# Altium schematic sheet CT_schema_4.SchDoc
size 252 x 159 mm
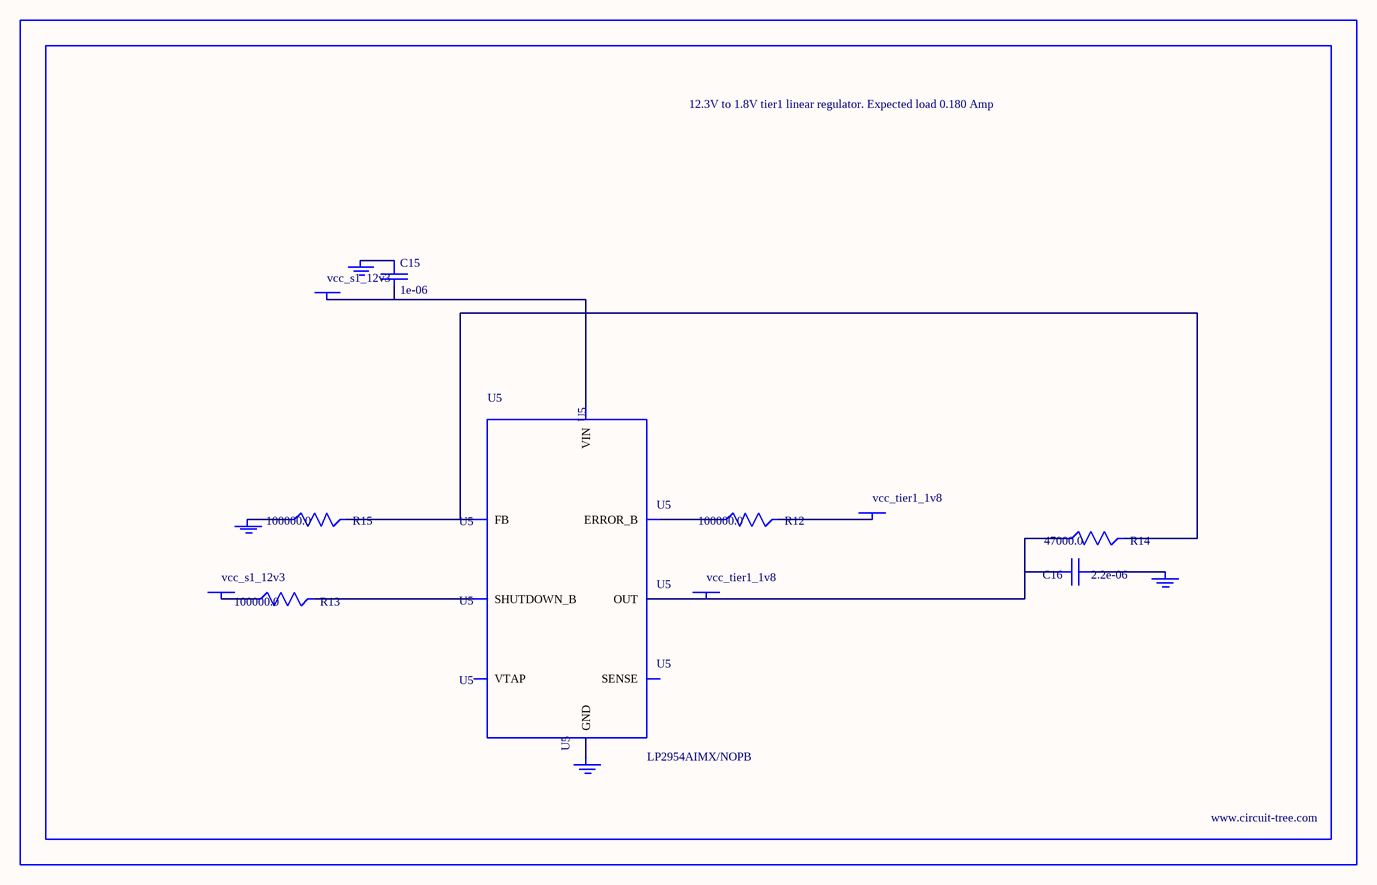
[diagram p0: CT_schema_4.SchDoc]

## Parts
BORDER3  (no value)
C15  1e-06  [EXV-9B]
C16  2.2e-06  [EXV-9B]
GND_INSTANCE_3_0  (no value)
GND_INSTANCE_3_1  (no value)
GND_INSTANCE_3_2  (no value)
GND_INSTANCE_3_3  (no value)
POWER_INSTANCE_3_0  vcc_s1_12v3
POWER_INSTANCE_3_1  vcc_tier1_1v8
POWER_INSTANCE_3_2  vcc_s1_12v3
POWER_INSTANCE_3_3  vcc_tier1_1v8
R12  100000.0  [R0603]
R13  100000.0  [R0603]
R14  47000.0  [R0603]
R15  100000.0  [R0603]
U5  LP2954AIMX/NOPB  [LP2954]

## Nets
NetC15_1: C15.1 GND_INSTANCE_3_2.0(GND)
NetC15_2: C15.2 POWER_INSTANCE_3_2.0(PWR) U5.8(VIN)
NetC16_1: C16.1 GND_INSTANCE_3_0.0(GND)
NetC16_2: C16.2 POWER_INSTANCE_3_3.0(PWR) R14.1 U5.1(OUT)
NetGND_INSTANCE_3_1_0: GND_INSTANCE_3_1.0(GND) R15.1
NetGND_INSTANCE_3_3_0: GND_INSTANCE_3_3.0(GND) U5.4(GND)
NetPOWER_INSTANCE_3_0_0: POWER_INSTANCE_3_0.0(PWR) R13.1
NetPOWER_INSTANCE_3_1_0: POWER_INSTANCE_3_1.0(PWR) R12.2
NetR12_1: R12.1 U5.5(ERROR_B)
NetR13_2: R13.2 U5.3(SHUTDOWN_B)
NetR14_2: R14.2 R15.2 U5.7(FB)

Not connected (* = marked no-connect by the designer): U5 2(SENSE) 6(VTAP)

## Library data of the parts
BORDER3 = BORDER_PAGE3
C15 = EDK105M050A9BAA
C16 = EDK225M050A9BAA
GND_INSTANCE_3_0-GND_INSTANCE_3_3 = GND
POWER_INSTANCE_3_0-POWER_INSTANCE_3_3 = PWR
R12 R13 R15 = RC0603JR-07100KL
R14 = RC0603JR-0747KL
